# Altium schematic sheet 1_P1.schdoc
size 307 x 218 mm; Symbol: Drawing-Symbol_A4; Device: Drawing-Symbol_A4; @Project Name: projetderechercehamine; @Page Count: 1; @Update Date: 2026-09-11; @Create Date: 2026-09-04; @Schematic Name: Schematic1; @Page No: 1; @Page Name: P1; Company: EasyEDA.com; Version: V1.0; Page Size: A4; @Create Time: 20:48:20; @Update Time: 20:31:46; Width: 1170; Height: 825; Region Start: 1; X Region Count: 6; Y Region Count: 4; Blade Width: 10; Title Block Position: 3; @Board Name: Board1
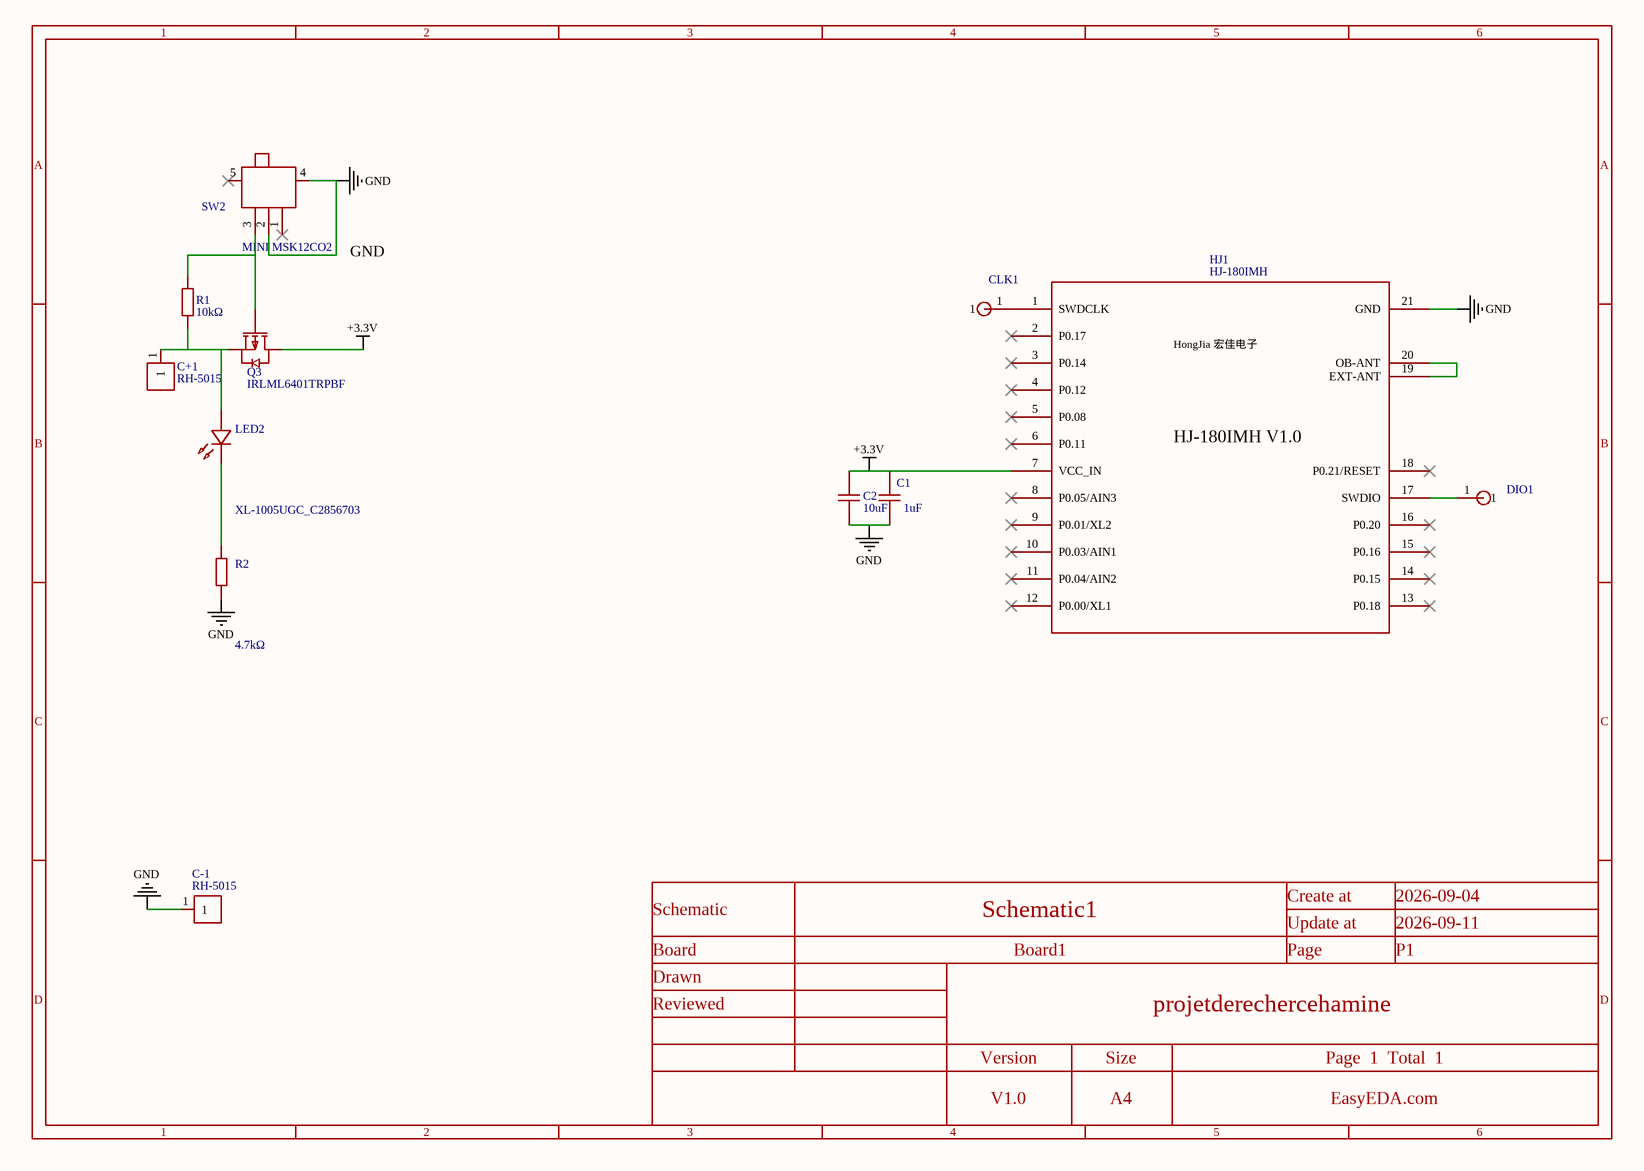
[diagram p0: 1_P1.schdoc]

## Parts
C1  1uF  [C0402]
C2  10uF  [C0402]
C+1  RH-5015  [SMD_RH-5015]
C-1  RH-5015  [SMD_RH-5015]
CLK1  TESTPOINT_D1.5mm  [TESTPOINT_D1.5MM]  (value not drawn)
DIO1  TESTPOINT_D1.5mm  [TESTPOINT_D1.5MM]  (value not drawn)
HJ1  HJ-180IMH  [HJ-180IMH(LGA21)]
LED2  XL-1005UGC_C2856703  [LED0402-RD_GREEN]
Q3  IRLML6401TRPBF  [SOT-23-3_L2.9-W1.3-P1.90-LS2.4-BR]
R1  10kΩ  [R0402]
R2  4.7kΩ  [R0402]
SW2  MINI MSK12CO2  [SW-SMD_MSK12CO2]

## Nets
+3.3V: C1.2 C2.2 HJ1.7(VCC_IN) Q3.3(D)
GND: C1.1 C2.1 C-1.1 HJ1.21(GND) R2.1 SW2.2 SW2.4
NetC+1_1: C+1.1 LED2.2(A) Q3.2(S) R1.1
NetCLK1_1: CLK1.1 HJ1.1(SWDCLK)
NetDIO1_1: DIO1.1 HJ1.17(SWDIO)
NetHJ1_19: HJ1.19(EXT-ANT) HJ1.20(OB-ANT)
NetLED2_1: LED2.1(K) R2.2
NetQ3_1: Q3.1(G) R1.2 SW2.3

Not connected (* = marked no-connect by the designer): HJ1 2(P0.17)* 3(P0.14)* 4(P0.12)* 5(P0.08)* 6(P0.11)* 8(P0.05/AIN3)* 9(P0.01/XL2)* 10(P0.03/AIN1)* 11(P0.04/AIN2)* 12(P0.00/XL1)* 13(P0.18)* 14(P0.15)* 15(P0.16)* 16(P0.20)* 18(P0.21/RESET)*; SW2 1* 5*

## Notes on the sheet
- GND

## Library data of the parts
C1 = CL05A105KA5NQNC: Manufacturer: SAMSUNG(三星); Symbol: 1u; Add into BOM: yes; Tolerance: ±10%; Voltage Rating: 25V; Temperature Coefficient: X5R
C2 = CL05A106MQ5NUNC: Manufacturer: SAMSUNG(三星); Symbol: 10u; Add into BOM: yes; Tolerance: ±20%; Voltage Rating: 6.3V; Temperature Coefficient: X5R
C+1 C-1 = RH-5015: Manufacturer: 荣和; Add into BOM: yes
CLK1 DIO1 = TESTPOINT_D1.5mm: Add into BOM: yes
HJ1 = HJ-180IMH: Add into BOM: yes
LED2 = XL-1005UGC_C2856703: Manufacturer: XINGLIGHT(成兴光); 3DModel: LED0402_L1.0-W0.5-H0.2; Add into BOM: yes
Q3 = IRLML6401TRPBF: Manufacturer: Infineon(英飞凌); 3DModel: SOT-23-3P_L2.9-W1.3-H1.0-LS2.4-P0.95; Add into BOM: yes
R1 = CR0402JF0103G: Manufacturer: LIZ(丽智电子); Add into BOM: yes; Tolerance: ±5%; Power(Watts): 62.5mW; Voltage-Supply(Max): 50V; Temperature Coefficient: ±200ppm/℃
R2 = ACR0402J4K7: Manufacturer: VO(翔胜); Symbol: 4.7K; Add into BOM: yes; Tolerance: ±5%; Power(Watts): 62.5mW; Voltage-Supply(Max): 50V; Temperature Coefficient: ±200ppm/℃
SW2 = MINI MSK12CO2: Manufacturer: SHOU HAN(首韩); Add into BOM: yes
